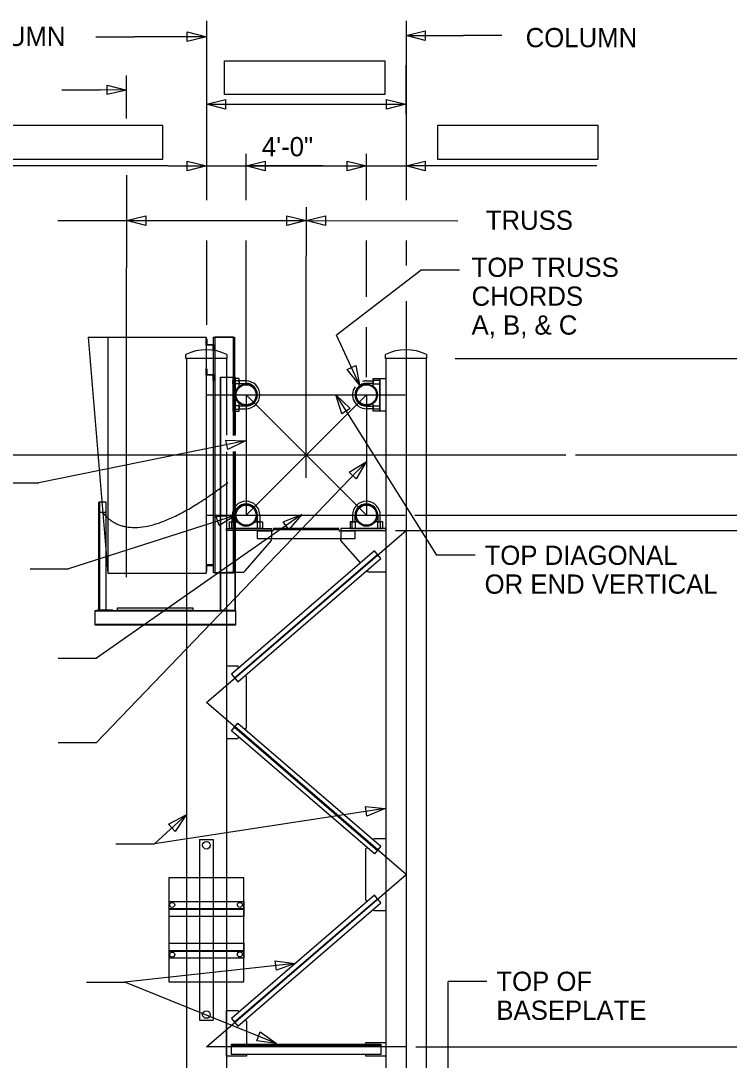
# Model space of a CAD drawing. Extents: x 3831399 to 3833095, y 499014 to 500202.
# Drawn here: x 3832893.8 to 3833000.9, y 499832.5 to 499989.7 of the extents above; entities that cross this region are included whole.
import ezdxf

# ---------------------------------------------------------------- set-up
doc = ezdxf.new("R2010")
doc.units = 0
for name, color, linetype in [('0-catwalk', 7, 'Continuous'), ('0-DEVICE ATTACH', 7, 'Continuous'), ('0-misc', 7, 'Continuous'), ('0-truss', 7, 'Continuous'), ('CenterLine', 7, 'Continuous'), ('Default', 7, 'Continuous'), ('DIM TXT', 7, 'Continuous'), ('PCENT', 7, 'Continuous'), ('sign', 7, 'Continuous'), ('structure', 7, 'Continuous')]:
    doc.layers.add(name, color=color, linetype=linetype)

msp = doc.modelspace()

# ---------------------------------------------------------------- linework, layer by layer
at = {"layer": '0-catwalk'}
for p, q in [((3832924.01, 499935.82), (3832926.25, 499935.82)), ((3832924.01, 499900.56), (3832924.01, 499935.82)), ((3832924.1, 499935.82), (3832926.17, 499935.82)), ((3832924.1, 499900.56), (3832924.1, 499935.82)), ((3832926.17, 499935.82), (3832926.17, 499927.05)), ((3832926.25, 499935.82), (3832926.25, 499927.05)), ((3832926.17, 499924.61), (3832926.17, 499900.56)), ((3832926.25, 499924.58), (3832926.25, 499900.56)), ((3832905.63, 499916.91), (3832905.63, 499900.66)), ((3832905.63, 499900.66), (3832905.63, 499916.91)), ((3832905.63, 499916.91), (3832905.75, 499916.91)), ((3832906.76, 499916.91), (3832905.63, 499916.91)), ((3832905.63, 499916.91), (3832905.63, 499900.66)), ((3832905.75, 499916.91), (3832905.75, 499900.66)), ((3832905.75, 499916.91), (3832905.75, 499900.66)), ((3832906.76, 499900.66), (3832906.76, 499916.91)), ((3832905.06, 499898.32), (3832905.06, 499900.56)), ((3832905.06, 499900.56), (3832926.27, 499900.56)), ((3832905.06, 499898.41), (3832905.06, 499900.48)), ((3832905.06, 499900.48), (3832926.27, 499900.48)), ((3832905.44, 499900.66), (3832907.71, 499900.66)), ((3832905.44, 499900.56), (3832905.44, 499900.66)), ((3832907.71, 499900.56), (3832905.44, 499900.56)), ((3832905.75, 499900.66), (3832905.63, 499900.66)), ((3832905.63, 499900.66), (3832906.76, 499900.66)), ((3832907.71, 499900.66), (3832907.71, 499900.56)), ((3832908.47, 499900.94), (3832919.84, 499900.94)), ((3832908.47, 499900.56), (3832908.47, 499900.94)), ((3832919.84, 499900.56), (3832908.47, 499900.56)), ((3832919.84, 499900.94), (3832919.84, 499900.56)), ((3832926.25, 499900.56), (3832924.01, 499900.56)), ((3832926.17, 499900.56), (3832924.1, 499900.56)), ((3832926.27, 499900.56), (3832926.27, 499898.32)), ((3832926.27, 499900.48), (3832926.27, 499898.41)), ((3832926.27, 499898.41), (3832905.06, 499898.41)), ((3832926.27, 499898.32), (3832905.06, 499898.32))]:
    msp.add_line(p, q, dxfattribs=at)
at = {"layer": '0-DEVICE ATTACH'}
for p, q in [((3832927.56, 499860.12), (3832916.19, 499860.12)), ((3832916.19, 499860.12), (3832916.19, 499844.38)), ((3832927.56, 499844.38), (3832927.56, 499860.12)), ((3832916.19, 499844.38), (3832922.91, 499844.38)), ((3832922.91, 499844.38), (3832927.56, 499844.38))]:
    msp.add_line(p, q, dxfattribs=at)
at = {"layer": '0-misc'}
for p, q in [((3832925.87, 499934.84), (3832925.87, 499935.31)), ((3832925.87, 499935.31), (3832926.87, 499935.31)), ((3832926.87, 499934.84), (3832925.87, 499934.84)), ((3832926.87, 499935.31), (3832926.87, 499934.84)), ((3832947.1, 499935.31), (3832947.1, 499934.84)), ((3832948.1, 499935.31), (3832947.1, 499935.31)), ((3832947.1, 499934.84), (3832948.1, 499934.84)), ((3832948.1, 499935.64), (3832949.05, 499935.64)), ((3832948.1, 499930.69), (3832948.1, 499935.64)), ((3832948.1, 499934.84), (3832948.1, 499935.31)), ((3832949.05, 499935.64), (3832949.05, 499930.69)), ((3832926.87, 499931.5), (3832925.87, 499931.5)), ((3832925.87, 499931.5), (3832925.87, 499931.02)), ((3832926.87, 499931.02), (3832926.87, 499931.5)), ((3832947.1, 499931.02), (3832947.1, 499931.5)), ((3832947.1, 499931.5), (3832948.1, 499931.5)), ((3832948.1, 499931.5), (3832948.1, 499931.02)), ((3832925.87, 499931.02), (3832926.87, 499931.02)), ((3832948.1, 499931.02), (3832947.1, 499931.02)), ((3832949.05, 499930.69), (3832948.1, 499930.69)), ((3832925.74, 499913.95), (3832926.22, 499913.95)), ((3832925.74, 499912.95), (3832925.74, 499913.95)), ((3832926.22, 499913.95), (3832926.22, 499912.95)), ((3832930.03, 499913.95), (3832929.56, 499913.95)), ((3832929.56, 499913.95), (3832929.56, 499912.95)), ((3832930.03, 499912.95), (3832930.03, 499913.95)), ((3832943.94, 499913.95), (3832944.41, 499913.95)), ((3832943.94, 499912.95), (3832943.94, 499913.95)), ((3832944.41, 499913.95), (3832944.41, 499912.95)), ((3832948.23, 499913.95), (3832947.76, 499913.95)), ((3832947.76, 499913.95), (3832947.76, 499912.95)), ((3832948.23, 499912.95), (3832948.23, 499913.95)), ((3832926.22, 499912.95), (3832925.74, 499912.95)), ((3832929.56, 499912.95), (3832930.03, 499912.95)), ((3832944.41, 499912.95), (3832943.94, 499912.95)), ((3832947.76, 499912.95), (3832948.23, 499912.95))]:
    msp.add_line(p, q, dxfattribs=at)
for points in [[(3832926.87, 499934.44), (3832926.87, 499935.64), (3832925.87, 499935.64), (3832925.87, 499930.69), (3832926.87, 499930.69), (3832926.87, 499931.89)], [(3832947.1, 499934.44), (3832947.1, 499935.64), (3832948.1, 499935.64), (3832948.1, 499930.69), (3832947.1, 499930.69), (3832947.1, 499931.89)], [(3832929.17, 499913.95), (3832930.36, 499913.95), (3832930.36, 499912.95), (3832925.41, 499912.95), (3832925.41, 499913.95), (3832926.61, 499913.95)], [(3832944.81, 499913.95), (3832943.61, 499913.95), (3832943.61, 499912.95), (3832948.56, 499912.95), (3832948.56, 499913.95), (3832947.36, 499913.95)]]:
    msp.add_lwpolyline(points, dxfattribs=at)
for centre, start, end in [((3832927.89, 499933.17), 128.5493, 231.4507), ((3832946.09, 499933.17), 308.5493, 51.4507), ((3832927.89, 499914.97), 218.5493, 321.4507), ((3832946.09, 499914.97), 218.5493, 321.4507)]:
    msp.add_arc(centre, 1.64, start, end, dxfattribs=at)
at = {"layer": '0-truss'}
for p, q in [((3832918.79, 499938.68), (3832918.79, 499939.25)), ((3832925, 499939.25), (3832925, 499938.68)), ((3832948.98, 499938.68), (3832948.98, 499939.25)), ((3832955.18, 499939.25), (3832955.18, 499938.68)), ((3832925, 499938.68), (3832918.79, 499938.68)), ((3832918.86, 499938.68), (3832918.86, 499860.2)), ((3832924.92, 499938.68), (3832924.92, 499927.05)), ((3832955.18, 499938.68), (3832948.98, 499938.68)), ((3832949.05, 499938.68), (3832949.05, 499826.25)), ((3832955.11, 499938.68), (3832955.11, 499826.25)), ((3832924.92, 499924.54), (3832924.92, 499860.2)), ((3832924.92, 499912.67), (3832924.92, 499912.95)), ((3832924.92, 499912.95), (3832931.75, 499912.95)), ((3832931.75, 499912.67), (3832924.92, 499912.67)), ((3832924.92, 499912.67), (3832924.92, 499906.35)), ((3832931.75, 499912.67), (3832924.92, 499912.67)), ((3832931.87, 499912.57), (3832929.59, 499912.57)), ((3832929.59, 499912.57), (3832929.59, 499911.44)), ((3832931.75, 499912.95), (3832931.75, 499912.67)), ((3832931.75, 499912.57), (3832931.75, 499912.67)), ((3832931.75, 499912.67), (3832931.75, 499912.67)), ((3832931.75, 499912.57), (3832931.75, 499911.44)), ((3832941.91, 499912.95), (3832932.06, 499912.95)), ((3832932.06, 499912.95), (3832932.06, 499912.76)), ((3832941.91, 499912.95), (3832932.06, 499912.95)), ((3832932.06, 499912.95), (3832932.06, 499912.79)), ((3832932.06, 499912.79), (3832941.91, 499912.79)), ((3832941.91, 499912.76), (3832941.91, 499912.95)), ((3832941.91, 499912.79), (3832941.91, 499912.95)), ((3832944.38, 499912.57), (3832942.1, 499912.57)), ((3832949.05, 499912.95), (3832942.22, 499912.95)), ((3832942.22, 499912.95), (3832942.22, 499912.67)), ((3832942.22, 499912.67), (3832949.05, 499912.67)), ((3832942.22, 499912.57), (3832942.22, 499912.67)), ((3832942.22, 499912.67), (3832942.22, 499912.67)), ((3832942.22, 499912.67), (3832949.05, 499912.67)), ((3832942.22, 499912.57), (3832942.22, 499911.44)), ((3832944.38, 499911.44), (3832944.38, 499912.57)), ((3832949.05, 499912.67), (3832949.05, 499912.95)), ((3832949.05, 499912.67), (3832949.05, 499906.35)), ((3832927.75, 499906.56), (3832931.75, 499911.15)), ((3832929.59, 499911.44), (3832944.38, 499911.44)), ((3832931.75, 499911.15), (3832931.75, 499911.44)), ((3832942.22, 499911.15), (3832942.22, 499911.44)), ((3832945.2, 499907.74), (3832942.22, 499911.15)), ((3832947.3, 499909.55), (3832925.68, 499890.91)), ((3832948.29, 499908.4), (3832947.3, 499909.55)), ((3832926.14, 499890.38), (3832947.76, 499909.01)), ((3832947.83, 499908.93), (3832926.21, 499890.3)), ((3832926.67, 499889.76), (3832948.29, 499908.4)), ((3832947.76, 499909.01), (3832947.83, 499908.93)), ((3832924.92, 499906.35), (3832927.57, 499906.35)), ((3832927.57, 499906.35), (3832927.75, 499906.56)), ((3832946.4, 499906.35), (3832946.19, 499906.59)), ((3832949.05, 499906.35), (3832946.4, 499906.35)), ((3832926.64, 499892.11), (3832924.92, 499892.11)), ((3832924.92, 499892.11), (3832924.92, 499881.17)), ((3832926.82, 499891.89), (3832926.64, 499892.11)), ((3832925.68, 499890.91), (3832926.67, 499889.76)), ((3832926.21, 499890.3), (3832926.14, 499890.38)), ((3832927.96, 499890.54), (3832927.78, 499890.72)), ((3832927.96, 499882.79), (3832927.96, 499890.54)), ((3832925.68, 499882.37), (3832926.67, 499883.52)), ((3832926.21, 499882.99), (3832926.14, 499882.91)), ((3832926.14, 499882.91), (3832947.76, 499864.27)), ((3832947.83, 499864.35), (3832926.21, 499882.99)), ((3832926.67, 499883.52), (3832948.29, 499864.89)), ((3832927.78, 499882.57), (3832927.96, 499882.79)), ((3832924.92, 499881.17), (3832926.64, 499881.17)), ((3832947.3, 499863.74), (3832925.68, 499882.37)), ((3832926.64, 499881.17), (3832926.82, 499881.39)), ((3832947.15, 499865.87), (3832947.33, 499866.09)), ((3832947.33, 499866.09), (3832949.05, 499866.09)), ((3832949.05, 499866.09), (3832949.05, 499855.15)), ((3832946.01, 499864.51), (3832946.19, 499864.69)), ((3832946.01, 499856.76), (3832946.01, 499864.51)), ((3832948.29, 499864.89), (3832947.3, 499863.74)), ((3832947.76, 499864.27), (3832947.83, 499864.35)), ((3832918.86, 499860.2), (3832918.86, 499844.47)), ((3832924.92, 499860.2), (3832924.92, 499844.47)), ((3832947.3, 499857.5), (3832925.68, 499838.86)), ((3832948.29, 499856.35), (3832947.3, 499857.5)), ((3832926.14, 499838.33), (3832947.76, 499856.96)), ((3832947.83, 499856.88), (3832926.21, 499838.25)), ((3832926.67, 499837.71), (3832948.29, 499856.35)), ((3832946.19, 499856.54), (3832946.01, 499856.76)), ((3832947.76, 499856.96), (3832947.83, 499856.88)), ((3832947.33, 499855.15), (3832947.15, 499855.37)), ((3832949.05, 499855.15), (3832947.33, 499855.15)), ((3832918.86, 499844.47), (3832918.86, 499826.25)), ((3832924.92, 499844.47), (3832924.92, 499826.25)), ((3832924.92, 499833.15), (3832924.92, 499840.06)), ((3832924.92, 499840.06), (3832926.64, 499840.06)), ((3832926.64, 499840.06), (3832926.82, 499839.84)), ((3832925.68, 499838.86), (3832926.67, 499837.71)), ((3832927.78, 499838.66), (3832927.96, 499838.44)), ((3832927.96, 499838.44), (3832927.96, 499834.95)), ((3832926.21, 499838.25), (3832926.14, 499838.33)), ((3832925.68, 499834.95), (3832948.29, 499834.95)), ((3832925.68, 499833.43), (3832925.68, 499834.95)), ((3832948.29, 499834.79), (3832925.68, 499834.79)), ((3832946.01, 499834.95), (3832946.01, 499835.23)), ((3832946.01, 499835.23), (3832949.05, 499835.23)), ((3832948.29, 499834.95), (3832948.29, 499833.43)), ((3832949.05, 499835.23), (3832949.05, 499833.15)), ((3832927.96, 499833.15), (3832924.92, 499833.15)), ((3832948.29, 499833.43), (3832925.68, 499833.43)), ((3832927.96, 499833.43), (3832927.96, 499833.15)), ((3832946.01, 499833.15), (3832946.01, 499833.43)), ((3832949.05, 499833.15), (3832946.01, 499833.15)), ((3832949.05, 499833.15), (3832946.01, 499833.15))]:
    msp.add_line(p, q, dxfattribs=at)
for points in [[(3832927.89, 499935.26), (3832926.87, 499935.26), (3832926.87, 499934.88), (3832927.89, 499934.88)], [(3832946.09, 499935.26), (3832947.1, 499935.26), (3832947.1, 499934.88), (3832946.09, 499934.88)], [(3832927.89, 499931.45), (3832926.87, 499931.45), (3832926.87, 499931.07), (3832927.89, 499931.07)], [(3832946.09, 499931.45), (3832947.1, 499931.45), (3832947.1, 499931.07), (3832946.09, 499931.07)], [(3832926.17, 499914.97), (3832926.17, 499913.95), (3832925.79, 499913.95), (3832925.79, 499914.97)], [(3832929.98, 499914.97), (3832929.98, 499913.95), (3832929.6, 499913.95), (3832929.6, 499914.97)], [(3832943.99, 499914.97), (3832943.99, 499913.95), (3832944.37, 499913.95), (3832944.37, 499914.97)], [(3832947.8, 499914.97), (3832947.8, 499913.95), (3832948.18, 499913.95), (3832948.18, 499914.97)]]:
    msp.add_lwpolyline(points, dxfattribs=at)
for centre, radius in [((3832927.89, 499933.17), 1.64), ((3832927.89, 499933.17), 1.52), ((3832946.09, 499933.17), 1.64), ((3832946.09, 499933.17), 1.52), ((3832927.89, 499914.97), 1.64), ((3832927.89, 499914.97), 1.52), ((3832946.09, 499914.97), 1.64), ((3832946.09, 499914.97), 1.52)]:
    msp.add_circle(centre, radius, dxfattribs=at)
for centre, radius, start, end in [((3832921.89, 499933.17), 6.82, 62.944, 117.056), ((3832952.08, 499933.17), 6.82, 62.944, 117.056), ((3832927.89, 499933.17), 2.1, 270, 90), ((3832927.89, 499933.17), 1.72, 270, 90), ((3832946.09, 499933.17), 2.1, 145.0207, 270), ((3832946.09, 499933.17), 1.72, 90, 270), ((3832946.09, 499933.17), 2.1, 90, 106.1224), ((3832927.89, 499914.97), 2.1, 0, 180), ((3832946.09, 499914.97), 2.1, 0, 180), ((3832927.89, 499914.97), 1.72, 0, 180), ((3832946.09, 499914.97), 1.72, 0, 180), ((3832931.87, 499912.76), 0.19, 270, 360), ((3832942.1, 499912.76), 0.19, 180, 270)]:
    msp.add_arc(centre, radius, start, end, dxfattribs=at)
at = {"layer": 'CenterLine'}
for p, q in [((3832952.08, 499942.23), (3832952.08, 499826.25)), ((3832922.01, 499933.17), (3832951.96, 499933.17)), ((3832927.89, 499933.17), (3832927.89, 499914.97)), ((3832927.89, 499914.97), (3832946.09, 499933.17)), ((3832946.09, 499914.97), (3832927.89, 499933.17)), ((3832946.09, 499933.17), (3832946.09, 499914.97)), ((3832885.2, 499924.07), (3832976.25, 499924.07)), ((3832922.01, 499914.97), (3832951.96, 499914.97)), ((3832921.89, 499886.64), (3832952.08, 499912.67)), ((3832952.08, 499860.62), (3832921.89, 499886.64)), ((3832921.89, 499834.59), (3832952.08, 499860.62)), ((3832952.08, 499834.59), (3832921.89, 499834.59))]:
    msp.add_line(p, q, dxfattribs=at)
at = {"layer": 'Default'}
for p, q in [((3832924.61, 499983.66), (3832948.86, 499983.66)), ((3832924.61, 499978.57), (3832924.61, 499983.66)), ((3832948.86, 499983.66), (3832948.86, 499978.57)), ((3832909.8, 499974.94), (3832909.8, 499981.47)), ((3832948.86, 499978.57), (3832924.61, 499978.57)), ((3832936.99, 499920.62), (3832936.99, 499954.17)), ((3832909.8, 499905.61), (3832909.8, 499952.36)), ((3832954.35, 499952.02), (3832941.55, 499942.2)), ((3832906.76, 499915.39), (3832905.63, 499915.39))]:
    msp.add_line(p, q, dxfattribs=at)
at = {"layer": 'DIM TXT'}
for p, q in [((3832921.89, 499989.73), (3832921.89, 499962.61)), ((3832952.08, 499989.73), (3832952.08, 499962.61)), ((3832905.19, 499987.32), (3832911.01, 499987.32)), ((3832921.89, 499987.31), (3832911.01, 499987.32)), ((3832952.08, 499987.5), (3832960.76, 499987.5)), ((3832966.58, 499987.5), (3832960.76, 499987.5)), ((3832921.89, 499982.61), (3832921.89, 499975.66)), ((3832952.05, 499983.03), (3832952.05, 499975.66)), ((3832900.02, 499979.3), (3832905.84, 499979.3)), ((3832909.8, 499979.24), (3832905.84, 499979.3)), ((3832921.89, 499977.11), (3832952.05, 499977.11)), ((3832915.29, 499973.87), (3832891.04, 499973.87)), ((3832915.29, 499968.78), (3832915.29, 499973.87)), ((3832981.11, 499973.88), (3832956.86, 499973.88)), ((3832956.86, 499973.88), (3832956.86, 499968.79)), ((3832981.11, 499968.79), (3832981.11, 499973.88)), ((3832927.89, 499962.61), (3832927.89, 499969.62)), ((3832946.08, 499962.61), (3832946.08, 499969.62)), ((3832891.04, 499968.78), (3832915.29, 499968.78)), ((3832916.07, 499967.79), (3832891.98, 499967.79)), ((3832916.07, 499967.79), (3832921.89, 499967.79)), ((3832921.89, 499967.79), (3832927.89, 499967.79)), ((3832939.49, 499967.79), (3832927.89, 499967.79)), ((3832927.89, 499967.79), (3832946.08, 499967.79)), ((3832940.27, 499967.79), (3832946.09, 499967.79)), ((3832946.09, 499967.79), (3832952.08, 499967.79)), ((3832963.69, 499967.79), (3832952.08, 499967.79)), ((3832956.86, 499968.79), (3832981.11, 499968.79)), ((3832980.95, 499967.79), (3832956.86, 499967.79)), ((3832909.8, 499966.36), (3832909.8, 499952.36)), ((3832936.99, 499961.54), (3832936.99, 499954.17)), ((3832899.44, 499959.52), (3832909.8, 499959.52)), ((3832909.8, 499959.52), (3832936.99, 499959.52)), ((3832936.99, 499959.52), (3832959.92, 499959.5)), ((3832921.89, 499956.51), (3832921.89, 499943.76)), ((3832927.89, 499934.62), (3832927.89, 499956.51)), ((3832946.08, 499947.98), (3832946.08, 499956.51)), ((3832952.08, 499956.51), (3832952.08, 499952.74)), ((3832960.17, 499952.02), (3832954.35, 499952.02)), ((3832952.08, 499947.35), (3832952.08, 499942.23)), ((3832945.05, 499934.67), (3832941.55, 499942.2)), ((3832946.08, 499935.86), (3832946.08, 499943.4)), ((3832959.5, 499938.68), (3833009.43, 499938.68)), ((3832941.46, 499933.16), (3832956.69, 499908.91)), ((3832927.83, 499926.2), (3832896.53, 499919.85)), ((3832977.71, 499924.07), (3833012.57, 499924.07)), ((3832946.04, 499923.04), (3832905.28, 499880.61)), ((3832890.71, 499919.85), (3832896.53, 499919.85)), ((3832926.37, 499914.97), (3832901.04, 499906.84)), ((3832936.31, 499915.06), (3832905.28, 499893.35)), ((3832953.42, 499914.97), (3833020.11, 499914.97)), ((3832950.5, 499912.67), (3833020.11, 499912.67)), ((3832962.51, 499908.91), (3832956.69, 499908.91)), ((3832895.22, 499906.84), (3832901.04, 499906.84)), ((3832899.46, 499893.35), (3832905.28, 499893.35)), ((3832899.46, 499880.61), (3832905.28, 499880.61)), ((3832948.92, 499870.62), (3832914.03, 499865.28)), ((3832918.82, 499869.64), (3832914.03, 499865.28)), ((3832908.21, 499865.28), (3832914.03, 499865.28)), ((3832908.21, 499865.28), (3832914.03, 499865.28)), ((3832935.29, 499847.19), (3832909.56, 499844.33)), ((3832903.74, 499844.33), (3832909.56, 499844.33)), ((3832903.74, 499844.33), (3832909.56, 499844.33)), ((3832932.47, 499835.05), (3832909.56, 499844.33)), ((3832958.46, 499826.25), (3832958.47, 499844.47)), ((3832964.29, 499844.47), (3832958.47, 499844.47)), ((3832953.54, 499834.59), (3833020.11, 499834.59))]:
    msp.add_line(p, q, dxfattribs=at)
for points in [[(3832918.98, 499988.04), (3832921.89, 499987.31), (3832918.98, 499986.59)], [(3832954.99, 499986.77), (3832952.08, 499987.5), (3832954.99, 499988.23)], [(3832906.9, 499980.01), (3832909.8, 499979.24), (3832906.88, 499978.56)], [(3832924.8, 499976.38), (3832921.89, 499977.11), (3832924.8, 499977.84)], [(3832949.14, 499977.84), (3832952.05, 499977.11), (3832949.14, 499976.38)], [(3832918.98, 499968.51), (3832921.89, 499967.79), (3832918.98, 499967.06)], [(3832930.8, 499967.06), (3832927.89, 499967.79), (3832930.8, 499968.51)], [(3832930.8, 499967.06), (3832927.89, 499967.79), (3832930.8, 499968.51)], [(3832943.17, 499968.51), (3832946.08, 499967.79), (3832943.17, 499967.06)], [(3832943.18, 499968.51), (3832946.09, 499967.79), (3832943.18, 499967.06)], [(3832954.99, 499967.06), (3832952.08, 499967.79), (3832954.99, 499968.51)], [(3832912.71, 499958.79), (3832909.8, 499959.52), (3832912.71, 499960.24)], [(3832934.08, 499960.24), (3832936.99, 499959.52), (3832934.08, 499958.79)], [(3832939.9, 499958.79), (3832936.99, 499959.52), (3832939.9, 499960.24)], [(3832944.48, 499937.62), (3832945.05, 499934.67), (3832943.16, 499937)], [(3832942.39, 499930.31), (3832941.46, 499933.16), (3832943.63, 499931.08)], [(3832924.84, 499926.33), (3832927.83, 499926.2), (3832925.13, 499924.91)], [(3832943.5, 499921.45), (3832946.04, 499923.04), (3832944.55, 499920.44)], [(3832923.38, 499914.77), (3832926.37, 499914.97), (3832923.82, 499913.39)], [(3832933.51, 499913.98), (3832936.31, 499915.06), (3832934.35, 499912.79)], [(3832945.93, 499870.9), (3832948.92, 499870.62), (3832946.15, 499869.46)], [(3832916.17, 499868.22), (3832918.82, 499869.64), (3832917.15, 499867.14)], [(3832932.31, 499847.59), (3832935.29, 499847.19), (3832932.47, 499846.14)], [(3832930.04, 499836.82), (3832932.47, 499835.05), (3832929.5, 499835.47)]]:
    msp.add_lwpolyline(points, close=True, dxfattribs=at)
at = {"layer": 'PCENT'}
msp.add_open_spline([(3832906.2, 499915.39), (3832911.05, 499909.15), (3832925.13, 499919.9)], degree=2, dxfattribs=at)
at = {"layer": 'sign'}
for p, q in [((3832904, 499941.91), (3832906.98, 499906.22)), ((3832904, 499941.91), (3832921.86, 499941.91)), ((3832906.98, 499941.91), (3832906.98, 499906.22)), ((3832921.86, 499941.91), (3832921.86, 499906.22)), ((3832921.86, 499940.69), (3832921.86, 499941.69)), ((3832922.8, 499940.69), (3832921.86, 499940.69)), ((3832921.95, 499941.59), (3832921.95, 499940.88)), ((3832922.05, 499940.79), (3832922.99, 499940.79)), ((3832922.9, 499939.89), (3832922.9, 499940.6)), ((3832922.99, 499906.25), (3832922.99, 499941.89)), ((3832922.99, 499941.89), (3832926.13, 499941.89)), ((3832922.99, 499940.79), (3832922.99, 499939.79)), ((3832925.98, 499941.89), (3832923.15, 499941.89)), ((3832923.15, 499941.89), (3832923.15, 499906.25)), ((3832925.98, 499927.03), (3832925.98, 499941.89)), ((3832926.13, 499941.89), (3832926.13, 499927.03)), ((3832921.86, 499936.14), (3832921.86, 499937.14)), ((3832922.8, 499936.14), (3832921.86, 499936.14)), ((3832921.95, 499937.04), (3832921.95, 499936.33)), ((3832922.05, 499936.24), (3832922.99, 499936.24)), ((3832922.9, 499935.34), (3832922.9, 499936.05)), ((3832922.99, 499936.24), (3832922.99, 499935.24)), ((3832925.98, 499906.25), (3832925.98, 499924.58)), ((3832926.13, 499924.58), (3832926.13, 499906.25)), ((3832922.9, 499908.25), (3832922.9, 499907.54)), ((3832922.99, 499907.35), (3832922.99, 499908.34)), ((3832906.98, 499906.22), (3832921.86, 499906.22)), ((3832921.86, 499907.44), (3832921.86, 499906.45)), ((3832922.8, 499907.44), (3832921.86, 499907.44)), ((3832921.95, 499906.54), (3832921.95, 499907.25)), ((3832922.05, 499907.35), (3832922.99, 499907.35)), ((3832926.13, 499906.25), (3832922.99, 499906.25)), ((3832923.15, 499906.25), (3832925.98, 499906.25))]:
    msp.add_line(p, q, dxfattribs=at)
for centre, start, end in [((3832921.86, 499941.59), 0, 90), ((3832922.05, 499940.88), 180, 270), ((3832922.8, 499940.6), 0, 90), ((3832922.99, 499939.89), 180, 270), ((3832921.86, 499937.04), 0, 90), ((3832922.05, 499936.33), 180, 270), ((3832922.8, 499936.05), 0, 90), ((3832922.99, 499935.34), 180, 270), ((3832922.99, 499908.25), 90, 180), ((3832921.86, 499906.54), 270, 0), ((3832922.05, 499907.25), 90, 180), ((3832922.8, 499907.54), 270, 0)]:
    msp.add_arc(centre, 0.0948, start, end, dxfattribs=at)
at = {"layer": 'structure'}
for p, q in [((3832920.86, 499865.9), (3832922.91, 499865.9)), ((3832920.86, 499865.9), (3832920.86, 499860.11)), ((3832922.91, 499865.9), (3832922.91, 499860.16)), ((3832920.86, 499860.11), (3832920.86, 499844.38)), ((3832922.91, 499860.16), (3832922.91, 499844.39)), ((3832916.19, 499856.57), (3832916.19, 499854.29)), ((3832916.19, 499856.57), (3832927.55, 499856.57)), ((3832927.56, 499856.57), (3832927.56, 499854.29)), ((3832916.19, 499855.48), (3832927.57, 499855.48)), ((3832916.19, 499855.38), (3832927.57, 499855.38)), ((3832927.58, 499854.29), (3832916.19, 499854.29)), ((3832916.19, 499850.24), (3832916.19, 499847.96)), ((3832916.19, 499850.24), (3832927.55, 499850.24)), ((3832927.56, 499850.24), (3832927.56, 499847.96)), ((3832916.19, 499849.15), (3832927.57, 499849.15)), ((3832916.19, 499849.05), (3832927.57, 499849.05)), ((3832927.58, 499847.96), (3832916.19, 499847.96)), ((3832920.86, 499844.38), (3832920.86, 499838.6)), ((3832922.91, 499844.39), (3832922.91, 499838.6)), ((3832920.86, 499838.6), (3832922.91, 499838.6))]:
    msp.add_line(p, q, dxfattribs=at)
for centre, radius in [((3832921.89, 499865.04), 0.569), ((3832916.72, 499856.04), 0.379), ((3832926.96, 499856.04), 0.379), ((3832916.72, 499848.52), 0.379), ((3832926.96, 499848.55), 0.379), ((3832921.89, 499839.45), 0.569)]:
    msp.add_circle(centre, radius, dxfattribs=at)

# ---------------------------------------------------------------- texts
at = {"layer": 'DIM TXT'}
for s, height, p in [('  COLUMN', 2.91, (3832881.56, 499985.92)), ('  COLUMN', 2.91, (3832968.01, 499985.73)), ('4\'-0"', 2.91, (3832930.28, 499969.24)), ('  TRUSS', 2.91, (3832961.98, 499958.12)), ('TOP TRUSS', 2.91, (3832961.99, 499951)), ('CHORDS ', 2.91, (3832961.99, 499946.63)), ('A, B, & C', 2.91, (3832961.99, 499942.27)), ('TOP DIAGONAL', 2.9099, (3832963.96, 499907.45)), ('OR END VERTICAL', 2.9099, (3832963.96, 499903.09)), ('TOP OF', 2.91, (3832965.74, 499843.02)), ('BASEPLATE', 2.91, (3832965.74, 499838.65))]:
    msp.add_text(s, height=height, dxfattribs=at).set_placement(p)

doc.saveas('drawing.dxf')
